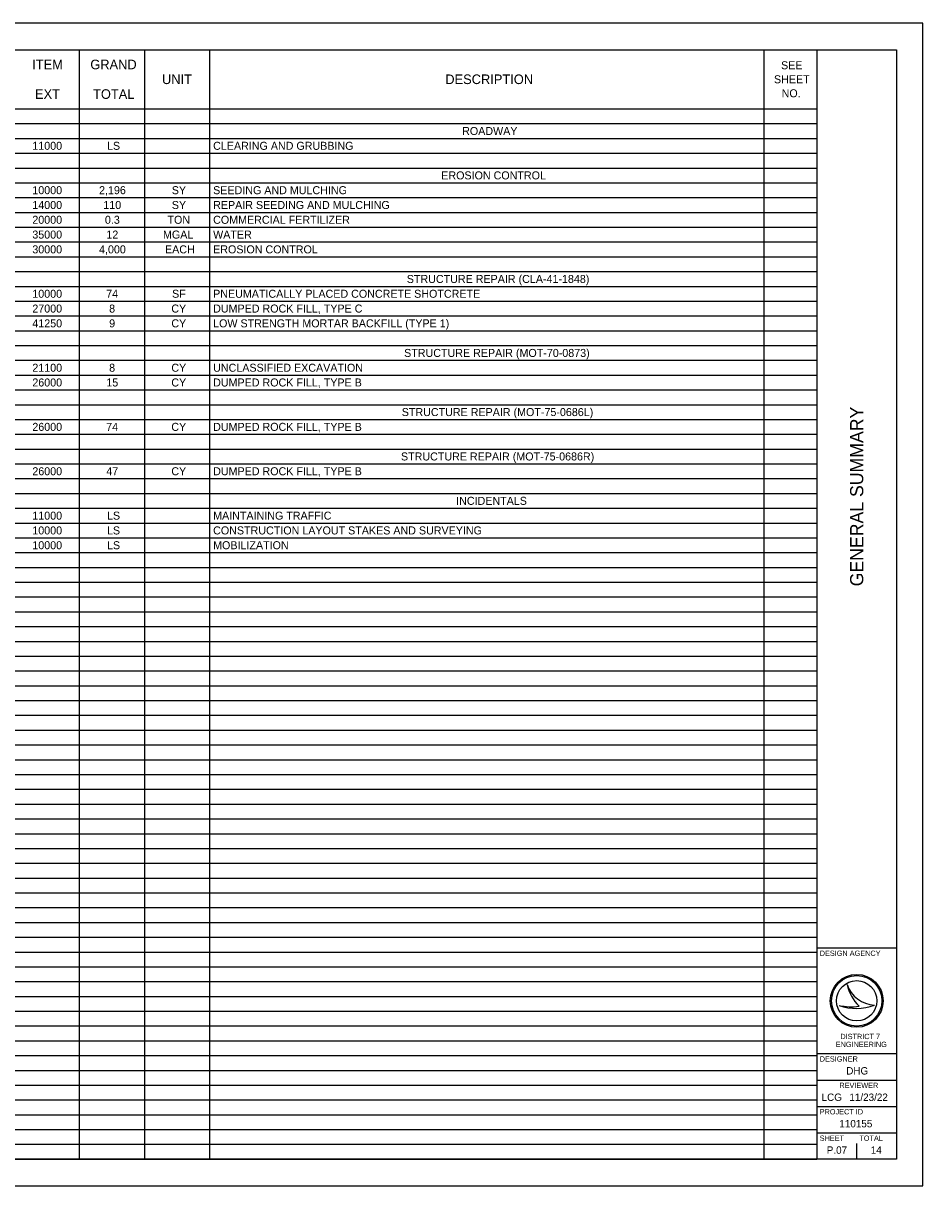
# Model space of a CAD drawing. Extents: x 0 to 34, y 0 to 22.
# Drawn here: x 16.97 to 34, y 0 to 22 of the extents above; entities that cross this region are included whole.
import ezdxf

# ---------------------------------------------------------------- set-up
doc = ezdxf.new("R2010")
doc.units = 0
for name, color, linetype in [('Default', 7, 'Continuous'), ('SH_Border', 7, 'Continuous'), ('SH_Cut_Line', 7, 'Continuous'), ('SH_Data', 7, 'Continuous')]:
    doc.layers.add(name, color=color, linetype=linetype)

msp = doc.modelspace()

# ---------------------------------------------------------------- linework, layer by layer
at = {"layer": 'Default'}
for p, q in [((1.5, 21.5), (31.997, 21.5)), ((18.033, 21.5), (18.033, 0.504)), ((19.268, 21.5), (19.268, 0.504)), ((20.503, 21.5), (20.503, 0.504)), ((30.993, 21.5), (30.993, 0.504)), ((31.997, 21.5), (31.997, 0.504)), ((1.5, 20.38), (31.997, 20.38)), ((1.5, 20.1), (31.997, 20.1)), ((1.5, 19.82), (31.997, 19.82)), ((1.5, 19.54), (31.997, 19.54)), ((1.5, 19.26), (31.997, 19.26)), ((1.5, 18.981), (31.997, 18.981)), ((1.5, 18.701), (31.997, 18.701)), ((1.5, 18.421), (31.997, 18.421)), ((1.5, 18.141), (31.997, 18.141)), ((1.5, 17.861), (31.997, 17.861)), ((1.5, 17.581), (31.997, 17.581)), ((1.5, 17.301), (31.997, 17.301)), ((1.5, 17.021), (31.997, 17.021)), ((1.5, 16.741), (31.997, 16.741)), ((1.5, 16.461), (31.997, 16.461)), ((1.5, 16.181), (31.997, 16.181)), ((1.5, 15.901), (31.997, 15.901)), ((1.5, 15.621), (31.997, 15.621)), ((1.5, 15.341), (31.997, 15.341)), ((1.5, 15.061), (31.997, 15.061)), ((1.5, 14.781), (31.997, 14.781)), ((1.5, 14.501), (31.997, 14.501)), ((1.5, 14.221), (31.997, 14.221)), ((1.5, 13.942), (31.997, 13.942)), ((1.5, 13.662), (31.997, 13.662)), ((1.5, 13.382), (31.997, 13.382)), ((1.5, 13.102), (31.997, 13.102)), ((1.5, 12.822), (31.997, 12.822)), ((1.5, 12.542), (31.997, 12.542)), ((1.5, 12.262), (31.997, 12.262)), ((1.5, 11.982), (31.997, 11.982)), ((1.5, 11.702), (31.997, 11.702)), ((1.5, 11.422), (31.997, 11.422)), ((1.5, 11.142), (31.997, 11.142)), ((1.5, 10.862), (31.997, 10.862)), ((1.5, 10.582), (31.997, 10.582)), ((1.5, 10.302), (31.997, 10.302)), ((1.5, 10.022), (31.997, 10.022)), ((1.5, 9.742), (31.997, 9.742)), ((1.5, 9.462), (31.997, 9.462)), ((1.5, 9.182), (31.997, 9.182)), ((1.5, 8.903), (31.997, 8.903)), ((1.5, 8.623), (31.997, 8.623)), ((1.5, 8.343), (31.997, 8.343)), ((1.5, 8.063), (31.997, 8.063)), ((1.5, 7.783), (31.997, 7.783)), ((1.5, 7.503), (31.997, 7.503)), ((1.5, 7.223), (31.997, 7.223)), ((1.5, 6.943), (31.997, 6.943)), ((1.5, 6.663), (31.997, 6.663)), ((1.5, 6.383), (31.997, 6.383)), ((1.5, 6.103), (31.997, 6.103)), ((1.5, 5.823), (31.997, 5.823)), ((1.5, 5.543), (31.997, 5.543)), ((1.5, 5.263), (31.997, 5.263)), ((1.5, 4.983), (31.997, 4.983)), ((1.5, 4.703), (31.997, 4.703)), ((1.5, 4.423), (31.997, 4.423)), ((1.5, 4.144), (31.997, 4.144)), ((1.5, 3.864), (31.997, 3.864)), ((1.5, 3.584), (31.997, 3.584)), ((1.5, 3.304), (31.997, 3.304)), ((1.5, 3.024), (31.997, 3.024)), ((1.5, 2.744), (31.997, 2.744)), ((1.5, 2.464), (31.997, 2.464)), ((1.5, 2.184), (31.997, 2.184)), ((1.5, 1.904), (31.997, 1.904)), ((1.5, 1.624), (31.997, 1.624)), ((1.5, 1.344), (31.997, 1.344)), ((1.5, 1.064), (31.997, 1.064)), ((1.5, 0.784), (31.997, 0.784)), ((1.5, 0.504), (31.997, 0.504))]:
    msp.add_line(p, q, dxfattribs=at)
at = {"layer": 'SH_Border'}
for p, q in [((32, 0.5), (32, 21.5)), ((32, 4.5), (33.5, 4.5)), ((32, 2.5), (33.5, 2.5)), ((32, 2), (33.5, 2)), ((32, 1.5), (33.5, 1.5)), ((32, 1), (33.5, 1))]:
    msp.add_line(p, q, dxfattribs=at)
msp.add_lwpolyline([(1.5, 21.5), (33.5, 21.5), (33.5, 0.5), (1.5, 0.5)], close=True, dxfattribs=at)
at = {"layer": 'SH_Cut_Line'}
msp.add_lwpolyline([(0, 0), (34, 0), (34, 22), (0, 22)], close=True, dxfattribs=at)
at = {"layer": 'SH_Data'}
for p, q in [((32.567, 3.81), (32.567, 3.81)), ((32.417, 3.41), (32.417, 3.41)), ((32.75, 3.5), (32.75, 3.5)), ((33.087, 3.419), (33.087, 3.419)), ((32.375, 0.675), (32.375, 0.675)), ((32.75, 0.5), (32.75, 0.8))]:
    msp.add_line(p, q, dxfattribs=at)
for radius in [0.5, 0.477, 0.477, 0.382]:
    msp.add_circle((32.75, 3.5), radius, dxfattribs=at)
for centre, radius, start, end in [((33.116, 3.998), 0.58, 198.9257, 198.9319), ((33.347, 3.97), 0.796, 191.6379, 191.6421), ((33.116, 3.998), 0.58, 198.9319, 267.1657), ((33.347, 3.97), 0.796, 191.6421, 226.0947), ((32.739, 4.37), 1.013, 251.4576, 290.0832), ((32.648, 4.654), 1.266, 259.4964, 259.4995), ((32.739, 4.37), 1.013, 251.4527, 251.4576), ((32.648, 4.654), 1.266, 259.4995, 276.6672)]:
    msp.add_arc(centre, radius, start, end, dxfattribs=at)

# ---------------------------------------------------------------- texts
at = {"layer": 'Default'}
for s, height, p in [('ITEM', 0.1818, (17.144, 21.129)), ('GRAND', 0.1818, (18.244, 21.129)), ('SEE ', 0.1515, (31.318, 21.129)), ('UNIT', 0.1818, (19.602, 20.849)), ('DESCRIPTION', 0.1818, (24.963, 20.849)), ('SHEET ', 0.1515, (31.184, 20.864)), ('EXT', 0.1818, (17.198, 20.569)), ('TOTAL', 0.1818, (18.296, 20.569)), ('NO.', 0.1515, (31.329, 20.599)), ('ROADWAY', 0.1515, (25.282, 19.885)), ('11000', 0.1515, (17.147, 19.605)), ('LS', 0.1515, (18.56, 19.605)), ('CLEARING AND GRUBBING', 0.1515, (20.569, 19.605)), ('EROSION CONTROL', 0.1515, (24.887, 19.045)), ('10000', 0.1515, (17.147, 18.765)), ('2,196', 0.1515, (18.41, 18.765)), ('SY', 0.1515, (19.787, 18.765)), ('SEEDING AND MULCHING', 0.1515, (20.569, 18.765)), ('14000', 0.1515, (17.147, 18.485)), ('110', 0.1515, (18.491, 18.485)), ('SY', 0.1515, (19.787, 18.485)), ('REPAIR SEEDING AND MULCHING', 0.1515, (20.569, 18.485)), ('20000', 0.1515, (17.147, 18.205)), ('0.3', 0.1515, (18.521, 18.205)), ('TON', 0.1515, (19.705, 18.205)), ('COMMERCIAL FERTILIZER', 0.1515, (20.569, 18.205)), ('35000', 0.1515, (17.147, 17.925)), ('12', 0.1515, (18.548, 17.925)), ('MGAL', 0.1515, (19.62, 17.925)), ('WATER', 0.1515, (20.569, 17.925)), ('30000', 0.1515, (17.147, 17.645)), ('4,000', 0.1515, (18.41, 17.645)), ('EACH', 0.1515, (19.658, 17.645)), ('EROSION CONTROL', 0.1515, (20.569, 17.645)), ('STRUCTURE REPAIR (CLA-41-1848)', 0.1515, (24.234, 17.085)), ('10000', 0.1515, (17.147, 16.805)), ('74', 0.1515, (18.545, 16.805)), ('SF', 0.1515, (19.792, 16.805)), ('PNEUMATICALLY PLACED CONCRETE SHOTCRETE', 0.1515, (20.569, 16.805)), ('27000', 0.1515, (17.147, 16.525)), ('8', 0.151, (18.601, 16.525)), ('CY', 0.1515, (19.778, 16.525)), ('DUMPED ROCK FILL, TYPE C', 0.1515, (20.569, 16.525)), ('41250', 0.1515, (17.147, 16.245)), ('9', 0.151, (18.602, 16.245)), ('CY', 0.1515, (19.778, 16.245)), ('LOW STRENGTH MORTAR BACKFILL (TYPE 1)', 0.1515, (20.569, 16.245)), ('STRUCTURE REPAIR (MOT-70-0873)', 0.1515, (24.184, 15.685)), ('21100', 0.1515, (17.147, 15.405)), ('8', 0.151, (18.601, 15.405)), ('CY', 0.1515, (19.778, 15.405)), ('UNCLASSIFIED EXCAVATION', 0.1515, (20.569, 15.405)), ('26000', 0.1515, (17.147, 15.126)), ('15', 0.1515, (18.548, 15.126)), ('CY', 0.1515, (19.778, 15.126)), ('DUMPED ROCK FILL, TYPE B', 0.1515, (20.569, 15.126)), ('STRUCTURE REPAIR (MOT-75-0686L)', 0.1515, (24.139, 14.566)), ('26000', 0.1515, (17.147, 14.286)), ('74', 0.1515, (18.545, 14.286)), ('CY', 0.1515, (19.778, 14.286)), ('DUMPED ROCK FILL, TYPE B', 0.1515, (20.569, 14.286)), ('STRUCTURE REPAIR (MOT-75-0686R)', 0.1515, (24.124, 13.726)), ('26000', 0.1515, (17.147, 13.446)), ('47', 0.1515, (18.547, 13.446)), ('CY', 0.1515, (19.778, 13.446)), ('DUMPED ROCK FILL, TYPE B', 0.1515, (20.569, 13.446)), ('INCIDENTALS', 0.1515, (25.169, 12.886)), ('11000', 0.1515, (17.147, 12.606)), ('LS', 0.1515, (18.56, 12.606)), ('MAINTAINING TRAFFIC', 0.1515, (20.569, 12.606)), ('10000', 0.1515, (17.147, 12.326)), ('LS', 0.1515, (18.56, 12.326)), ('CONSTRUCTION LAYOUT STAKES AND SURVEYING', 0.1515, (20.569, 12.326)), ('10000', 0.1515, (17.147, 12.046)), ('LS', 0.1515, (18.56, 12.046)), ('MOBILIZATION', 0.1515, (20.569, 12.046))]:
    msp.add_text(s, height=height, dxfattribs=at).set_placement(p)
at = {"layer": 'SH_Data'}
msp.add_text('GENERAL SUMMARY', height=0.25, rotation=90, dxfattribs=at).set_placement((32.875, 11.344))
for s, height, p in [('DESIGN AGENCY', 0.1, (32.05, 4.35)), ('DISTRICT 7', 0.1, (32.441, 2.775)), ('ENGINEERING', 0.1, (32.353, 2.625)), ('DESIGNER', 0.1, (32.05, 2.35)), ('DHG', 0.14, (32.552, 2.105)), ('REVIEWER', 0.1, (32.422, 1.85)), ('LCG', 0.14, (32.085, 1.605)), ('11/23/22', 0.14, (32.611, 1.605)), ('PROJECT ID', 0.1, (32.05, 1.35)), ('110155', 0.14, (32.421, 1.105)), ('SHEET', 0.1, (32.05, 0.85)), ('TOTAL', 0.1, (32.8, 0.85)), ('P.07', 0.14, (32.183, 0.605)), ('14', 0.14, (33.016, 0.605))]:
    msp.add_text(s, height=height, dxfattribs=at).set_placement(p)

doc.saveas('drawing.dxf')
